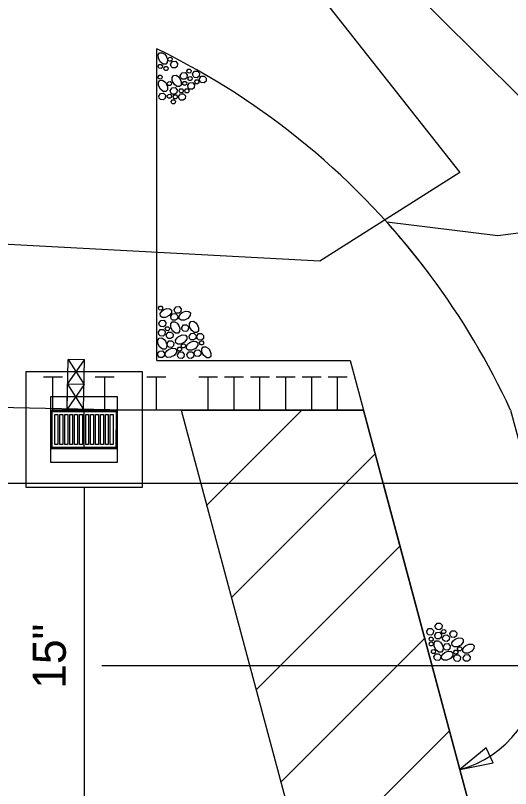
# Model space of a CAD drawing. Extents: x -20 to 509, y -659 to 21.
# Drawn here: x 65.09 to 94.98, y -377.49 to -330.79 of the extents above; entities that cross this region are included whole.
import ezdxf

# ---------------------------------------------------------------- set-up
doc = ezdxf.new("R2010")
doc.units = 0
for name, color, linetype in [('Auto Dimensioning', 7, 'Continuous'), ('Default', 7, 'Continuous'), ('Exist Hydro Stream or Body of Water', 7, 'Continuous'), ('Exist Vegetation Woods Line', 7, 'Continuous'), ('Mis Object Lines', 7, 'Continuous'), ('Miscellaneous Lines CELL', 7, 'Continuous'), ('Prop EOT', 7, 'Continuous'), ('Prop Horizontal Alignment', 7, 'Continuous'), ('Sub End Bent Cap Lines CELL', 7, 'Continuous'), ('Sup Concrete Girder Lines', 7, 'Continuous'), ('Text', 7, 'Continuous')]:
    doc.layers.add(name, color=color, linetype=linetype)

# ---------------------------------------------------------------- blocks, each defined once
blk = doc.blocks.new('AH')
at = {"layer": 'Sub End Bent Cap Lines CELL'}
blk.add_lwpolyline([(0, 0), (-1.25, 0.312), (-1.25, -0.312)], close=True, dxfattribs=at)

msp = doc.modelspace()

# ---------------------------------------------------------------- linework, layer by layer
at = {"layer": 'Auto Dimensioning'}
msp.add_arc((90.229, -370.052), 6.513, 285, 360, dxfattribs=at)
at = {"layer": 'Default'}
for p, q in [((94.209, -344.105), (87.515, -343.284)), ((94.209, -344.105), (87.515, -343.284)), ((99.199, -343.425), (94.209, -344.105)), ((99.199, -343.425), (94.209, -344.105)), ((68.202, -354.565), (68.262, -351.566)), ((68.232, -353.065), (69.262, -351.586)), ((69.262, -351.586), (68.262, -351.566)), ((68.262, -351.566), (69.232, -353.085)), ((69.202, -354.585), (69.262, -351.586)), ((67.921, -352.635), (66.775, -352.635)), ((67.921, -352.635), (66.775, -352.635)), ((67.348, -354.635), (67.348, -352.635)), ((67.348, -354.635), (67.348, -352.635)), ((71.046, -352.635), (69.9, -352.635)), ((71.046, -352.635), (69.9, -352.635)), ((70.473, -354.635), (70.473, -352.635)), ((70.473, -354.635), (70.473, -352.635)), ((74.171, -352.635), (73.025, -352.635)), ((74.171, -352.635), (73.025, -352.635)), ((73.598, -354.635), (73.598, -352.635)), ((73.598, -354.635), (73.598, -352.635)), ((77.296, -352.635), (76.15, -352.635)), ((77.296, -352.635), (76.15, -352.635)), ((76.723, -354.635), (76.723, -352.635)), ((76.723, -354.635), (76.723, -352.635)), ((78.858, -352.635), (77.713, -352.635)), ((78.858, -352.635), (77.713, -352.635)), ((78.286, -354.635), (78.286, -352.635)), ((78.286, -354.635), (78.286, -352.635)), ((80.421, -352.635), (79.275, -352.635)), ((80.421, -352.635), (79.275, -352.635)), ((79.848, -354.635), (79.848, -352.635)), ((79.848, -354.635), (79.848, -352.635)), ((81.983, -352.635), (80.838, -352.635)), ((81.983, -352.635), (80.838, -352.635)), ((81.411, -354.635), (81.411, -352.635)), ((81.411, -354.635), (81.411, -352.635)), ((83.546, -352.635), (82.4, -352.635)), ((83.546, -352.635), (82.4, -352.635)), ((82.973, -354.635), (82.973, -352.635)), ((82.973, -354.635), (82.973, -352.635)), ((85.108, -352.635), (83.963, -352.635)), ((85.108, -352.635), (83.963, -352.635)), ((84.536, -354.635), (84.536, -352.635)), ((84.536, -354.635), (84.536, -352.635)), ((68.202, -354.565), (68.232, -353.065)), ((69.232, -353.085), (68.202, -354.565)), ((69.232, -353.085), (68.232, -353.065)), ((68.232, -353.065), (69.202, -354.585)), ((71.744, -354.635), (25.003, -353.701)), ((86.098, -354.635), (67.348, -354.635)), ((86.098, -354.635), (67.348, -354.635)), ((69.202, -354.585), (68.202, -354.565)), ((69.23, -354.632), (69.23, -354.632)), ((94.36, -385.469), (86.098, -354.635)), ((94.982, -354.635), (96.165, -359.052)), ((67.23, -355.798), (67.23, -355.798)), ((69.23, -355.799), (69.23, -355.799)), ((71.23, -355.799), (71.23, -355.799)), ((69.229, -356.965), (69.229, -356.965)), ((87.282, -359.052), (93.177, -381.052))]:
    msp.add_line(p, q, dxfattribs=at)
for points in [[(72.728, -359.3), (65.728, -359.297), (65.731, -352.297), (72.731, -352.3)], [(71.229, -357.8), (67.229, -357.798), (67.23, -353.798), (71.23, -353.799)]]:
    msp.add_lwpolyline(points, close=True, dxfattribs=at)
for points in [[(71.229, -356.966), (67.229, -356.965), (67.23, -354.631), (71.23, -354.633), (71.229, -356.966)], [(71.167, -356.904), (67.292, -356.902), (67.292, -354.694), (71.167, -354.695), (71.167, -356.904)], [(69.219, -356.892), (67.302, -356.892), (67.303, -354.704), (69.22, -354.705), (69.219, -356.892)], [(67.646, -356.71), (67.469, -356.71), (67.47, -354.887), (67.647, -354.887), (67.646, -356.71)], [(67.943, -356.71), (67.766, -356.71), (67.766, -354.887), (67.943, -354.887), (67.943, -356.71)], [(68.24, -356.71), (68.063, -356.71), (68.063, -354.887), (68.24, -354.887), (68.24, -356.71)], [(68.537, -356.71), (68.359, -356.71), (68.36, -354.887), (68.537, -354.887), (68.537, -356.71)], [(68.833, -356.71), (68.656, -356.71), (68.657, -354.887), (68.834, -354.887), (68.833, -356.71)], [(69.13, -356.71), (68.953, -356.71), (68.954, -354.887), (69.131, -354.887), (69.13, -356.71)], [(71.156, -356.893), (69.24, -356.892), (69.24, -354.705), (71.157, -354.706), (71.156, -356.893)], [(69.505, -356.71), (69.328, -356.71), (69.329, -354.887), (69.506, -354.887), (69.505, -356.71)], [(69.802, -356.71), (69.625, -356.71), (69.626, -354.887), (69.803, -354.887), (69.802, -356.71)], [(70.099, -356.71), (69.922, -356.71), (69.922, -354.888), (70.1, -354.888), (70.099, -356.71)], [(70.396, -356.711), (70.219, -356.711), (70.219, -354.888), (70.396, -354.888), (70.396, -356.711)], [(70.693, -356.711), (70.516, -356.711), (70.516, -354.888), (70.693, -354.888), (70.693, -356.711)], [(70.99, -356.711), (70.812, -356.711), (70.813, -354.888), (70.99, -354.888), (70.99, -356.711)]]:
    msp.add_lwpolyline(points, dxfattribs=at)
for start, end in [(36.716, 41.9334), (24.7352, 36.716)]:
    msp.add_arc((53.715, -373.646), 45.435, start, end, dxfattribs=at)
at = {"layer": 'Exist Hydro Stream or Body of Water'}
msp.add_lwpolyline([(131.08, -386.838), (129.369, -382.245), (128.25, -382.169), (117.417, -368.872), (114.493, -357.356), (113.975, -353.41), (95.563, -335.727), (80.713, -320.952)], dxfattribs=at)
at = {"layer": 'Exist Vegetation Woods Line'}
msp.add_lwpolyline([(76.7, -320.952), (91.912, -340.27), (83.469, -345.626), (-3.076, -340.993)], dxfattribs=at)
at = {"layer": 'Mis Object Lines'}
for p, q in [((75.098, -354.635), (83.36, -385.469)), ((76.635, -360.37), (82.369, -354.635)), ((78.129, -365.947), (86.804, -357.271)), ((79.623, -371.523), (88.299, -362.848)), ((81.118, -377.1), (89.793, -368.425)), ((82.612, -382.677), (91.287, -374.001))]:
    msp.add_line(p, q, dxfattribs=at)
msp.add_lwpolyline([(75.098, -354.635), (86.098, -354.635), (94.36, -385.469)], dxfattribs=at)
at = {"layer": 'Miscellaneous Lines CELL'}
for points in [[(74.177, -333.231), (74.26, -333.441), (74.244, -333.634), (74.157, -333.725), (74.001, -333.722), (73.823, -333.583), (73.716, -333.369), (73.712, -333.166), (73.793, -333.052), (73.954, -333.042), (74.098, -333.134), (74.183, -333.24)], [(74.295, -333.413), (74.363, -333.318), (74.47, -333.311), (74.545, -333.389), (74.534, -333.497), (74.468, -333.552), (74.362, -333.545), (74.312, -333.496), (74.296, -333.413)], [(73.706, -333.842), (73.773, -333.746), (73.88, -333.74), (73.955, -333.818), (73.944, -333.926), (73.878, -333.981), (73.772, -333.973), (73.722, -333.925), (73.706, -333.842)], [(74.053, -333.97), (74.12, -333.874), (74.228, -333.868), (74.302, -333.945), (74.291, -334.054), (74.225, -334.109), (74.119, -334.101), (74.069, -334.053), (74.053, -333.97)], [(74.457, -333.726), (74.569, -333.566), (74.748, -333.556), (74.873, -333.685), (74.855, -333.866), (74.744, -333.958), (74.568, -333.945), (74.484, -333.864), (74.457, -333.726)], [(73.695, -334.493), (73.763, -334.397), (73.87, -334.391), (73.945, -334.468), (73.934, -334.577), (73.867, -334.632), (73.761, -334.624), (73.712, -334.576), (73.695, -334.493)], [(75.016, -334.591), (75.099, -334.8), (75.082, -334.993), (74.995, -335.084), (74.839, -335.081), (74.661, -334.943), (74.554, -334.728), (74.55, -334.526), (74.631, -334.412), (74.792, -334.401), (74.937, -334.493), (75.021, -334.599)], [(75.038, -334.41), (75.15, -334.251), (75.329, -334.24), (75.453, -334.369), (75.435, -334.55), (75.325, -334.642), (75.148, -334.629), (75.065, -334.549), (75.038, -334.41)], [(75.44, -334.129), (75.507, -334.033), (75.615, -334.027), (75.689, -334.104), (75.679, -334.213), (75.612, -334.268), (75.506, -334.26), (75.456, -334.212), (75.44, -334.129)], [(75.78, -334.321), (75.892, -334.161), (76.071, -334.151), (76.195, -334.28), (76.177, -334.461), (76.067, -334.553), (75.89, -334.54), (75.807, -334.459), (75.78, -334.321)], [(74.192, -334.887), (74.275, -335.097), (74.259, -335.289), (74.172, -335.381), (74.015, -335.378), (73.838, -335.239), (73.731, -335.024), (73.727, -334.822), (73.808, -334.708), (73.969, -334.697), (74.113, -334.79), (74.198, -334.895)], [(74.255, -334.886), (74.323, -334.791), (74.43, -334.784), (74.504, -334.862), (74.494, -334.97), (74.427, -335.025), (74.321, -335.018), (74.272, -334.969), (74.255, -334.886)], [(75.18, -334.868), (75.247, -334.773), (75.354, -334.766), (75.429, -334.844), (75.418, -334.952), (75.352, -335.007), (75.246, -335), (75.196, -334.951), (75.18, -334.868)], [(75.486, -335.015), (75.598, -334.855), (75.777, -334.845), (75.902, -334.974), (75.884, -335.155), (75.773, -335.247), (75.596, -335.234), (75.513, -335.153), (75.486, -335.015)], [(75.505, -334.584), (75.572, -334.489), (75.679, -334.483), (75.754, -334.56), (75.743, -334.668), (75.677, -334.724), (75.571, -334.716), (75.521, -334.667), (75.505, -334.584)], [(75.916, -334.78), (75.983, -334.684), (76.09, -334.678), (76.165, -334.755), (76.154, -334.864), (76.088, -334.919), (75.982, -334.911), (75.932, -334.863), (75.916, -334.78)], [(76.196, -334.622), (76.308, -334.463), (76.487, -334.453), (76.611, -334.582), (76.593, -334.762), (76.483, -334.854), (76.306, -334.842), (76.223, -334.761), (76.196, -334.622)], [(74.431, -335.314), (74.543, -335.154), (74.722, -335.144), (74.847, -335.273), (74.829, -335.454), (74.718, -335.546), (74.541, -335.533), (74.458, -335.452), (74.431, -335.314)], [(74.971, -335.316), (75.038, -335.22), (75.146, -335.214), (75.22, -335.292), (75.209, -335.4), (75.143, -335.455), (75.037, -335.447), (74.987, -335.399), (74.971, -335.316)], [(75.316, -335.321), (75.383, -335.225), (75.49, -335.219), (75.565, -335.296), (75.554, -335.405), (75.488, -335.46), (75.382, -335.452), (75.332, -335.404), (75.316, -335.321)], [(73.734, -335.652), (73.846, -335.492), (74.025, -335.482), (74.149, -335.611), (74.131, -335.792), (74.021, -335.884), (73.844, -335.871), (73.761, -335.79), (73.734, -335.652)], [(74.255, -335.651), (74.323, -335.555), (74.43, -335.549), (74.504, -335.627), (74.494, -335.735), (74.427, -335.79), (74.321, -335.783), (74.272, -335.734), (74.255, -335.651)], [(74.609, -335.684), (74.677, -335.589), (74.784, -335.583), (74.859, -335.66), (74.848, -335.768), (74.782, -335.824), (74.675, -335.816), (74.626, -335.768), (74.609, -335.684)], [(74.935, -335.681), (75.047, -335.522), (75.226, -335.512), (75.351, -335.641), (75.333, -335.821), (75.222, -335.913), (75.045, -335.901), (74.962, -335.82), (74.935, -335.681)], [(74.495, -335.989), (74.562, -335.893), (74.669, -335.887), (74.744, -335.964), (74.733, -336.073), (74.667, -336.128), (74.561, -336.12), (74.511, -336.072), (74.495, -335.989)], [(73.723, -348.445), (73.79, -348.349), (73.898, -348.343), (73.972, -348.421), (73.961, -348.529), (73.895, -348.584), (73.789, -348.577), (73.739, -348.528), (73.723, -348.445)], [(74.677, -348.547), (74.789, -348.388), (74.968, -348.378), (75.092, -348.507), (75.074, -348.687), (74.964, -348.779), (74.787, -348.767), (74.704, -348.686), (74.677, -348.547)], [(74.013, -348.568), (74.223, -348.485), (74.415, -348.501), (74.507, -348.588), (74.504, -348.745), (74.365, -348.922), (74.151, -349.03), (73.948, -349.033), (73.834, -348.952), (73.824, -348.791), (73.916, -348.647), (74.022, -348.562)], [(74.466, -348.969), (74.578, -348.81), (74.757, -348.799), (74.882, -348.928), (74.864, -349.109), (74.753, -349.201), (74.576, -349.188), (74.493, -349.108), (74.466, -348.969)], [(75.152, -348.737), (75.362, -348.654), (75.554, -348.671), (75.646, -348.758), (75.643, -348.914), (75.504, -349.092), (75.289, -349.199), (75.087, -349.203), (74.973, -349.122), (74.962, -348.96), (75.055, -348.816), (75.16, -348.732)], [(73.748, -349.369), (73.86, -349.21), (74.039, -349.199), (74.163, -349.328), (74.145, -349.509), (74.035, -349.601), (73.858, -349.588), (73.775, -349.508), (73.748, -349.369)], [(74.924, -349.482), (75.007, -349.691), (74.99, -349.884), (74.903, -349.975), (74.747, -349.972), (74.57, -349.833), (74.462, -349.619), (74.459, -349.416), (74.54, -349.303), (74.701, -349.292), (74.845, -349.384), (74.929, -349.49)], [(76.063, -349.454), (76.146, -349.664), (76.129, -349.857), (76.042, -349.948), (75.886, -349.945), (75.708, -349.806), (75.601, -349.592), (75.598, -349.389), (75.678, -349.275), (75.84, -349.265), (75.984, -349.357), (76.068, -349.463)], [(73.716, -349.922), (73.828, -349.763), (74.007, -349.753), (74.132, -349.882), (74.114, -350.063), (74.003, -350.154), (73.827, -350.142), (73.743, -350.061), (73.717, -349.923)], [(74.133, -349.696), (74.2, -349.6), (74.307, -349.594), (74.382, -349.671), (74.371, -349.78), (74.305, -349.835), (74.199, -349.827), (74.149, -349.779), (74.133, -349.696)], [(75.125, -349.64), (75.237, -349.481), (75.416, -349.471), (75.541, -349.599), (75.523, -349.78), (75.412, -349.872), (75.235, -349.859), (75.152, -349.779), (75.125, -349.64)], [(74.144, -350.458), (74.228, -350.667), (74.211, -350.86), (74.124, -350.951), (73.968, -350.948), (73.79, -350.809), (73.683, -350.595), (73.679, -350.393), (73.76, -350.279), (73.921, -350.268), (74.065, -350.36), (74.15, -350.466)], [(74.19, -350.081), (74.302, -349.921), (74.481, -349.911), (74.605, -350.04), (74.587, -350.221), (74.477, -350.313), (74.3, -350.3), (74.217, -350.219), (74.19, -350.081)], [(74.949, -350.174), (75.158, -350.091), (75.351, -350.108), (75.442, -350.195), (75.439, -350.351), (75.301, -350.529), (75.086, -350.636), (74.884, -350.64), (74.77, -350.559), (74.759, -350.397), (74.851, -350.253), (74.957, -350.169)], [(75.574, -350.16), (75.686, -350), (75.865, -349.99), (75.989, -350.119), (75.971, -350.3), (75.86, -350.392), (75.684, -350.379), (75.601, -350.298), (75.574, -350.16)], [(76.035, -350.167), (76.147, -350.007), (76.326, -349.997), (76.45, -350.126), (76.432, -350.307), (76.321, -350.398), (76.145, -350.386), (76.062, -350.305), (76.035, -350.167)], [(74.24, -350.605), (74.352, -350.446), (74.531, -350.436), (74.655, -350.564), (74.637, -350.745), (74.527, -350.837), (74.35, -350.824), (74.267, -350.744), (74.24, -350.605)], [(75.1, -350.736), (75.167, -350.64), (75.274, -350.634), (75.349, -350.711), (75.338, -350.82), (75.272, -350.875), (75.166, -350.867), (75.116, -350.819), (75.1, -350.736)], [(75.599, -350.549), (75.809, -350.466), (76.001, -350.482), (76.093, -350.569), (76.09, -350.726), (75.951, -350.903), (75.736, -351.01), (75.534, -351.014), (75.42, -350.933), (75.409, -350.772), (75.502, -350.628), (75.607, -350.543)], [(76.198, -350.552), (76.265, -350.456), (76.372, -350.45), (76.447, -350.528), (76.436, -350.636), (76.37, -350.691), (76.264, -350.683), (76.214, -350.635), (76.198, -350.552)], [(73.672, -351.221), (73.784, -351.062), (73.963, -351.052), (74.087, -351.181), (74.069, -351.361), (73.959, -351.453), (73.782, -351.441), (73.699, -351.36), (73.672, -351.221)], [(74.318, -350.976), (74.528, -350.893), (74.72, -350.909), (74.812, -350.996), (74.809, -351.153), (74.67, -351.33), (74.455, -351.437), (74.253, -351.441), (74.139, -351.36), (74.128, -351.199), (74.221, -351.055), (74.327, -350.97)], [(74.861, -351.281), (74.973, -351.121), (75.152, -351.111), (75.276, -351.24), (75.258, -351.421), (75.148, -351.513), (74.971, -351.5), (74.888, -351.419), (74.861, -351.281)], [(74.868, -350.93), (74.936, -350.835), (75.043, -350.829), (75.118, -350.906), (75.107, -351.014), (75.04, -351.069), (74.934, -351.062), (74.885, -351.013), (74.868, -350.93)], [(75.439, -351.274), (75.551, -351.115), (75.73, -351.104), (75.854, -351.233), (75.836, -351.414), (75.726, -351.506), (75.549, -351.493), (75.466, -351.413), (75.439, -351.274)], [(75.874, -351.157), (75.986, -350.998), (76.164, -350.987), (76.289, -351.116), (76.271, -351.297), (76.16, -351.389), (75.984, -351.376), (75.901, -351.296), (75.874, -351.157)], [(76.808, -350.986), (76.891, -351.196), (76.875, -351.389), (76.788, -351.48), (76.632, -351.477), (76.454, -351.338), (76.347, -351.124), (76.343, -350.921), (76.424, -350.807), (76.585, -350.797), (76.729, -350.889), (76.814, -350.995)], [(90.432, -367.668), (90.544, -367.508), (90.723, -367.498), (90.848, -367.627), (90.83, -367.808), (90.719, -367.9), (90.542, -367.887), (90.459, -367.806), (90.432, -367.668)], [(89.918, -367.988), (90.03, -367.829), (90.209, -367.819), (90.333, -367.948), (90.315, -368.128), (90.205, -368.22), (90.028, -368.208), (89.945, -368.127), (89.918, -367.988)], [(90.401, -368.221), (90.513, -368.062), (90.692, -368.052), (90.816, -368.181), (90.798, -368.361), (90.688, -368.453), (90.511, -368.44), (90.428, -368.36), (90.401, -368.221)], [(90.817, -367.994), (90.885, -367.899), (90.992, -367.893), (91.066, -367.97), (91.056, -368.078), (90.989, -368.133), (90.883, -368.126), (90.834, -368.077), (90.817, -367.994)], [(91.32, -368.132), (91.432, -367.972), (91.611, -367.962), (91.735, -368.091), (91.717, -368.272), (91.607, -368.363), (91.43, -368.351), (91.347, -368.27), (91.32, -368.132)], [(90.065, -368.445), (90.132, -368.349), (90.239, -368.343), (90.314, -368.42), (90.303, -368.529), (90.237, -368.584), (90.131, -368.576), (90.081, -368.528), (90.065, -368.445)], [(90.874, -368.379), (90.986, -368.22), (91.165, -368.21), (91.29, -368.339), (91.272, -368.519), (91.161, -368.611), (90.985, -368.599), (90.901, -368.518), (90.874, -368.379)], [(91.633, -368.473), (91.843, -368.39), (92.035, -368.407), (92.127, -368.494), (92.124, -368.65), (91.985, -368.827), (91.77, -368.935), (91.568, -368.938), (91.454, -368.857), (91.443, -368.696), (91.536, -368.552), (91.642, -368.468)], [(90.065, -368.741), (90.132, -368.645), (90.239, -368.639), (90.314, -368.716), (90.303, -368.825), (90.237, -368.88), (90.131, -368.872), (90.081, -368.824), (90.065, -368.741)], [(90.829, -368.756), (90.912, -368.966), (90.895, -369.158), (90.808, -369.25), (90.652, -369.247), (90.475, -369.108), (90.367, -368.894), (90.364, -368.691), (90.445, -368.577), (90.606, -368.567), (90.75, -368.659), (90.834, -368.765)], [(90.924, -368.904), (91.036, -368.744), (91.215, -368.734), (91.34, -368.863), (91.322, -369.044), (91.211, -369.136), (91.034, -369.123), (90.951, -369.042), (90.924, -368.904)], [(91.784, -369.035), (91.851, -368.939), (91.959, -368.933), (92.033, -369.01), (92.022, -369.119), (91.956, -369.174), (91.85, -369.166), (91.8, -369.118), (91.784, -369.035)], [(92.283, -368.847), (92.493, -368.764), (92.686, -368.781), (92.777, -368.868), (92.774, -369.024), (92.635, -369.202), (92.421, -369.309), (92.218, -369.313), (92.105, -369.232), (92.094, -369.071), (92.186, -368.926), (92.292, -368.842)], [(90.2, -369.201), (90.267, -369.105), (90.374, -369.099), (90.449, -369.177), (90.438, -369.285), (90.372, -369.34), (90.266, -369.333), (90.216, -369.284), (90.2, -369.201)], [(90.356, -369.52), (90.468, -369.361), (90.647, -369.351), (90.772, -369.48), (90.754, -369.66), (90.643, -369.752), (90.467, -369.739), (90.383, -369.659), (90.357, -369.52)], [(91.003, -369.274), (91.212, -369.191), (91.405, -369.208), (91.496, -369.295), (91.493, -369.451), (91.354, -369.629), (91.14, -369.736), (90.937, -369.74), (90.824, -369.659), (90.813, -369.498), (90.905, -369.353), (91.011, -369.269)], [(91.545, -369.579), (91.657, -369.42), (91.836, -369.41), (91.961, -369.539), (91.943, -369.719), (91.832, -369.811), (91.656, -369.798), (91.572, -369.718), (91.546, -369.579)], [(91.553, -369.229), (91.62, -369.133), (91.727, -369.127), (91.802, -369.205), (91.791, -369.313), (91.725, -369.368), (91.619, -369.36), (91.569, -369.312), (91.553, -369.229)], [(92.123, -369.573), (92.236, -369.413), (92.414, -369.403), (92.539, -369.532), (92.521, -369.713), (92.41, -369.805), (92.234, -369.792), (92.151, -369.711), (92.124, -369.573)]]:
    msp.add_lwpolyline(points, dxfattribs=at)
at = {"layer": 'Prop EOT'}
msp.add_line((-3.076, -359.052), (237.897, -359.052), dxfattribs=at)
at = {"layer": 'Prop Horizontal Alignment'}
msp.add_line((70.294, -370.052), (237.897, -370.052), dxfattribs=at)
msp.add_line((70.294, -370.052), (237.897, -370.052), dxfattribs=at)
at = {"layer": 'Sup Concrete Girder Lines'}
for p, q in [((73.63, -351.635), (73.63, -332.809)), ((73.63, -351.635), (73.63, -332.809)), ((85.294, -351.635), (86.098, -354.635)), ((69.23, -354.632), (69.23, -354.632)), ((67.23, -355.798), (67.23, -355.798)), ((69.23, -355.799), (69.23, -355.799)), ((71.23, -355.799), (71.23, -355.799)), ((69.229, -356.965), (69.229, -356.965)), ((69.232, -359.299), (69.227, -398.052))]:
    msp.add_line(p, q, dxfattribs=at)
for points in [[(73.63, -351.635), (85.294, -351.635)], [(71.229, -356.966), (67.229, -356.965), (67.23, -354.631), (71.23, -354.633), (71.229, -356.966)], [(71.167, -356.904), (67.292, -356.902), (67.292, -354.694), (71.167, -354.695), (71.167, -356.904)], [(69.219, -356.892), (67.302, -356.892), (67.303, -354.704), (69.22, -354.705), (69.219, -356.892)], [(67.646, -356.71), (67.469, -356.71), (67.47, -354.887), (67.647, -354.887), (67.646, -356.71)], [(67.943, -356.71), (67.766, -356.71), (67.766, -354.887), (67.943, -354.887), (67.943, -356.71)], [(68.24, -356.71), (68.063, -356.71), (68.063, -354.887), (68.24, -354.887), (68.24, -356.71)], [(68.537, -356.71), (68.359, -356.71), (68.36, -354.887), (68.537, -354.887), (68.537, -356.71)], [(68.833, -356.71), (68.656, -356.71), (68.657, -354.887), (68.834, -354.887), (68.833, -356.71)], [(69.13, -356.71), (68.953, -356.71), (68.954, -354.887), (69.131, -354.887), (69.13, -356.71)], [(71.156, -356.893), (69.24, -356.892), (69.24, -354.705), (71.157, -354.706), (71.156, -356.893)], [(69.505, -356.71), (69.328, -356.71), (69.329, -354.887), (69.506, -354.887), (69.505, -356.71)], [(69.802, -356.71), (69.625, -356.71), (69.626, -354.887), (69.803, -354.887), (69.802, -356.71)], [(70.099, -356.71), (69.922, -356.71), (69.922, -354.888), (70.1, -354.888), (70.099, -356.71)], [(70.396, -356.711), (70.219, -356.711), (70.219, -354.888), (70.396, -354.888), (70.396, -356.711)], [(70.693, -356.711), (70.516, -356.711), (70.516, -354.888), (70.693, -354.888), (70.693, -356.711)], [(70.99, -356.711), (70.812, -356.711), (70.813, -354.888), (70.99, -354.888), (70.99, -356.711)]]:
    msp.add_lwpolyline(points, dxfattribs=at)
for points in [[(72.728, -359.3), (65.728, -359.297), (65.731, -352.297), (72.731, -352.3)], [(71.229, -357.8), (67.229, -357.798), (67.23, -353.798), (71.23, -353.799)]]:
    msp.add_lwpolyline(points, close=True, dxfattribs=at)
for start, end in [(36.716, 64.0036), (24.7352, 36.716)]:
    msp.add_arc((53.715, -373.646), 45.435, start, end, dxfattribs=at)

# ---------------------------------------------------------------- block references
at = {"layer": 'Auto Dimensioning', "xscale": 1.6, "yscale": 1.5999999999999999, "rotation": -154.7315158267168}
msp.add_blockref('AH', (91.915, -376.343), dxfattribs=at)

# ---------------------------------------------------------------- texts
at = {"layer": 'Text'}
msp.add_text('15"', height=2, rotation=90, dxfattribs=at).set_placement((68.126, -371.461))

doc.saveas('drawing.dxf')
